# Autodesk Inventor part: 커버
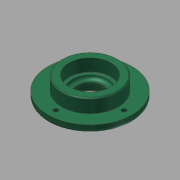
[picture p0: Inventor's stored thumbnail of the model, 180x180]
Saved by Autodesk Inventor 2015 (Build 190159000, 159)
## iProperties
Company: 한국ATC센터
Created: 2014-10
Part Number: 커버
Document SubType Name: Modeling
Designer: KYOUNG IL JANG
Density: 7.86 g/cm^3
Mass: 351.567 g
Surface Area: 161.165 cm^2
Volume: 44.7286 cm^3
Material: 강철, 연강
Appearance: Steel
Author: KYOUNG IL JANG
Revision Number: 1
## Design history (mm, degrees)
sketch "스케치1"
  geometry: C1 r 40 at (0, 0); 1 further point
  constraints: 1 centre point, 1 coincident
  dimensions: "d0" = 80 diameter of C1
extrude "돌출1" new body sketch "스케치1" distance "d1" = 7; taper "d2" = 0 deg
sketch "스케치2"
  geometry: C1 r 27 at (0, 0); 1 further point
  constraints: 1 centre point, 1 coincident
  dimensions: "d3" = 54 diameter of C1
extrude "돌출2" join sketch "스케치2" distance "d4" = 13; taper "d5" = 0 deg
sketch "스케치3"
  geometry: C1 r 20 at (0, 0); 1 further point
  constraints: 1 centre point, 1 coincident
  dimensions: "d6" = 40 diameter of C1
extrude "돌출3" join sketch "스케치3" distance "d7" = 5; taper "d8" = 0 deg
hole "구멍1" diameter "d11" = 25; stored, may be unused: countersink angle "d15" = 90 deg, drill point angle "d17" = 118 deg; dims "d9" = 10, "d10" = 10, "d12" = 6, "d13" = 32, "d14" = 8.3, "d16" = 8
hole "구멍2" diameter "d20" = 34; stored, may be unused: countersink angle "d24" = 90 deg, drill point angle "d26" = 0 deg; dims "d18" = 10, "d19" = 10, "d21" = 6, "d22" = 40, "d23" = 12, "d25" = 3
fillet "모깎기2" dims "d34" = 3
fillet "모깎기1" dims "d27" = 0.3
chamfer "모따기1" distance "d28" = 1; stored, may be unused: second distance "d29" = 2, angle "d30" = 45 deg
chamfer "모따기2" distance "d31" = 1.2; stored, may be unused: second distance "d32" = 2, angle "d33" = 30 deg
sketch "스케치4" dims "d35" = 65
  geometry: 3 further points
  constraints: 2 horizontal alignment, 1 coincident, 2 other
hole "구멍3" sketch "스케치4" at (32.5, 0) diameter "d36" = 4.5; stored, may be unused: countersink angle "d40" = 90 deg, drill point angle "d42" = 118 deg; dims "d37" = 6, "d38" = 8, "d39" = 4.4, "d41" = 13
node "솔리드1"
pattern_circular "원형 패턴1" dims angle "d44" = 360 deg
